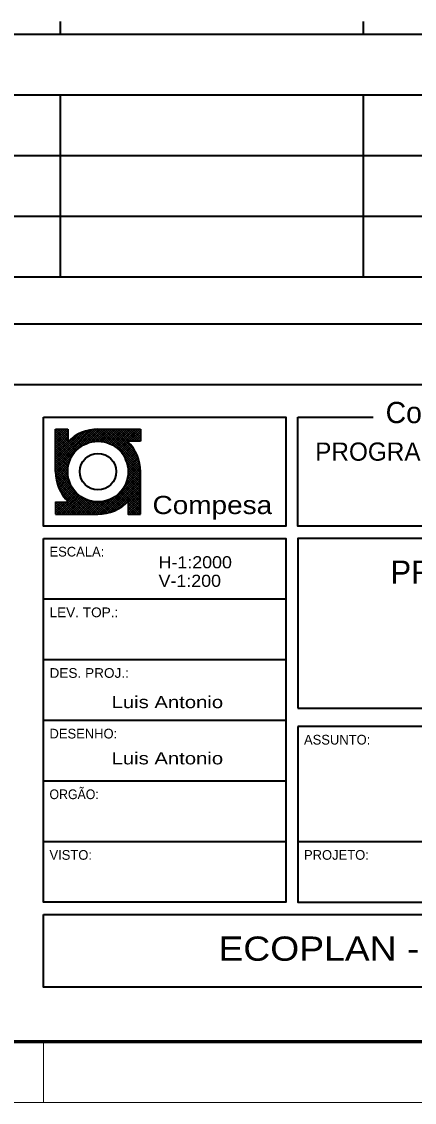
# Model space of a CAD drawing. Extents: x 949 to 2631, y -1701 to -513.
# Drawn here: x 2253.7 to 2383.4, y -1700.7 to -1344.3 of the extents above; entities that cross this region are included whole.
import ezdxf

# ---------------------------------------------------------------- set-up
doc = ezdxf.new("R2010")
doc.units = 0
doc.header["$LTSCALE"] = 1.2
for name, color, linetype, lineweight in [('1', 7, 'Continuous', 13), ('10', 7, 'Continuous', 13), ('11', 7, 'Continuous', 13), ('5', 7, 'Continuous', 13), ('6', 7, 'Continuous', 60), ('7', 7, 'Continuous', 35)]:
    doc.layers.add(name, color=color, linetype=linetype, lineweight=lineweight)

msp = doc.modelspace()

# ---------------------------------------------------------------- linework, layer by layer
at = {"layer": '1'}
for p, q in [((2264.926, -1478.868), (2265.067, -1478.728)), ((2264.926, -1479.575), (2265.774, -1478.728)), ((2264.926, -1480.283), (2266.481, -1478.728)), ((2264.926, -1480.99), (2267.188, -1478.728)), ((2264.926, -1481.697), (2267.895, -1478.728)), ((2264.926, -1482.404), (2268.602, -1478.728)), ((2264.926, -1492.303), (2278.49, -1478.739)), ((2264.926, -1491.596), (2277.739, -1478.783)), ((2264.926, -1490.889), (2276.942, -1478.873)), ((2264.926, -1490.182), (2276.086, -1479.022)), ((2268.926, -1482.694), (2264.959, -1478.728)), ((2268.926, -1481.987), (2265.667, -1478.728)), ((2268.926, -1481.28), (2266.374, -1478.728)), ((2268.926, -1480.573), (2267.081, -1478.728)), ((2268.926, -1479.866), (2267.788, -1478.728)), ((2268.926, -1479.158), (2268.495, -1478.728)), ((2268.926, -1482.93), (2268.926, -1478.728)), ((2273.764, -1484.172), (2279.209, -1478.728)), ((2275.172, -1483.472), (2279.916, -1478.728)), ((2276.243, -1483.108), (2280.623, -1478.728)), ((2280.395, -1482.849), (2276.491, -1478.945)), ((2281.27, -1483.017), (2277.104, -1478.852)), ((2277.162, -1482.896), (2281.33, -1478.728)), ((2282.277, -1483.317), (2277.742, -1478.783)), ((2277.988, -1482.777), (2282.037, -1478.728)), ((2283.535, -1483.868), (2278.408, -1478.741)), ((2278.734, -1482.738), (2282.744, -1478.728)), ((2292.921, -1492.547), (2279.102, -1478.728)), ((2279.425, -1482.754), (2283.451, -1478.728)), ((2292.892, -1491.811), (2279.809, -1478.728)), ((2280.086, -1482.8), (2284.159, -1478.728)), ((2292.819, -1491.03), (2280.516, -1478.728)), ((2280.696, -1482.897), (2284.866, -1478.728)), ((2292.69, -1490.195), (2281.223, -1478.728)), ((2281.281, -1483.02), (2285.573, -1478.728)), ((2281.838, -1483.169), (2286.28, -1478.728)), ((2292.493, -1489.29), (2281.93, -1478.728)), ((2282.364, -1483.351), (2286.987, -1478.728)), ((2292.206, -1488.296), (2282.637, -1478.728)), ((2282.875, -1483.547), (2287.694, -1478.728)), ((2291.759, -1487.142), (2283.344, -1478.728)), ((2283.353, -1483.775), (2288.401, -1478.728)), ((2283.822, -1484.014), (2289.108, -1478.728)), ((2291.041, -1485.717), (2284.051, -1478.728)), ((2284.259, -1484.284), (2289.815, -1478.728)), ((2284.688, -1484.562), (2290.523, -1478.728)), ((2288.758, -1482.728), (2284.758, -1478.728)), ((2285.089, -1484.868), (2291.23, -1478.728)), ((2289.466, -1482.728), (2285.466, -1478.728)), ((2285.48, -1485.185), (2291.937, -1478.728)), ((2285.846, -1485.525), (2292.644, -1478.728)), ((2290.173, -1482.728), (2286.173, -1478.728)), ((2290.88, -1482.728), (2286.88, -1478.728)), ((2291.587, -1482.728), (2287.587, -1478.728)), ((2292.294, -1482.728), (2288.294, -1478.728)), ((2292.926, -1482.652), (2289.001, -1478.728)), ((2292.926, -1481.945), (2289.708, -1478.728)), ((2292.926, -1481.238), (2290.415, -1478.728)), ((2292.926, -1480.531), (2291.122, -1478.728)), ((2292.926, -1479.824), (2291.83, -1478.728)), ((2292.926, -1479.117), (2292.537, -1478.728)), ((2264.926, -1483.111), (2268.926, -1479.111)), ((2264.926, -1489.475), (2275.154, -1479.247)), ((2271.528, -1486.003), (2264.926, -1479.401)), ((2264.926, -1488.768), (2274.105, -1479.589)), ((2264.926, -1483.818), (2268.926, -1479.818)), ((2264.926, -1488.061), (2272.882, -1480.104)), ((2271.208, -1486.39), (2264.926, -1480.108)), ((2264.926, -1484.525), (2268.926, -1480.525)), ((2270.891, -1486.781), (2264.926, -1480.815)), ((2264.926, -1487.354), (2271.269, -1481.01)), ((2264.926, -1485.232), (2268.926, -1481.232)), ((2270.606, -1487.203), (2264.926, -1481.522)), ((2264.926, -1485.939), (2268.926, -1481.939)), ((2270.328, -1487.632), (2264.926, -1482.23)), ((2272.235, -1485.296), (2269.404, -1482.465)), ((2272.626, -1484.979), (2269.78, -1482.134)), ((2273.016, -1484.663), (2270.166, -1481.813)), ((2273.442, -1484.382), (2270.562, -1481.501)), ((2273.871, -1484.103), (2270.976, -1481.209)), ((2274.334, -1483.859), (2271.402, -1480.927)), ((2274.802, -1483.621), (2271.838, -1480.656)), ((2275.308, -1483.419), (2272.292, -1480.403)), ((2275.819, -1483.223), (2272.76, -1480.164)), ((2276.375, -1483.072), (2273.24, -1479.937)), ((2276.941, -1482.931), (2273.737, -1479.727)), ((2277.552, -1482.834), (2274.253, -1479.535)), ((2278.19, -1482.766), (2274.784, -1479.359)), ((2278.862, -1482.731), (2275.331, -1479.2)), ((2279.601, -1482.763), (2275.899, -1479.06)), ((2289.351, -1482.728), (2292.926, -1479.153)), ((2290.058, -1482.728), (2292.926, -1479.86)), ((2290.765, -1482.728), (2292.926, -1480.567)), ((2291.472, -1482.728), (2292.926, -1481.274)), ((2292.179, -1482.728), (2292.926, -1481.981)), ((2264.926, -1486.646), (2268.926, -1482.646)), ((2270.08, -1488.091), (2264.926, -1482.937)), ((2269.842, -1488.56), (2264.926, -1483.644)), ((2269.636, -1489.061), (2264.926, -1484.351)), ((2269.44, -1489.572), (2264.926, -1485.058)), ((2269.285, -1490.124), (2264.926, -1485.765)), ((2271.881, -1485.649), (2269.045, -1482.813)), ((2286.2, -1485.879), (2289.033, -1483.045)), ((2286.533, -1486.253), (2289.372, -1483.414)), ((2286.849, -1486.644), (2289.702, -1483.791)), ((2287.148, -1487.052), (2290.014, -1484.186)), ((2287.426, -1487.481), (2290.314, -1484.593)), ((2287.688, -1487.926), (2290.605, -1485.009)), ((2287.926, -1488.395), (2290.878, -1485.444)), ((2288.147, -1488.882), (2291.137, -1485.891)), ((2292.887, -1482.728), (2292.926, -1482.688)), ((2269.139, -1490.685), (2264.926, -1486.472)), ((2269.042, -1491.295), (2264.926, -1487.179)), ((2268.968, -1491.928), (2264.926, -1487.886)), ((2268.933, -1492.6), (2264.926, -1488.594)), ((2268.957, -1493.332), (2264.926, -1489.301)), ((2264.933, -1493.003), (2270.371, -1487.566)), ((2264.962, -1493.681), (2269.67, -1488.973)), ((2292.926, -1493.259), (2287.785, -1488.118)), ((2292.926, -1493.966), (2288.336, -1489.377)), ((2288.343, -1489.393), (2291.386, -1486.35)), ((2288.514, -1489.928), (2291.618, -1486.825)), ((2288.664, -1490.486), (2291.833, -1487.317)), ((2288.776, -1491.081), (2292.034, -1487.823)), ((2288.872, -1491.692), (2292.221, -1488.343)), ((2288.888, -1493.09), (2292.531, -1489.447)), ((2288.907, -1492.364), (2292.385, -1488.886)), ((2269.035, -1494.117), (2264.926, -1490.008)), ((2269.191, -1494.98), (2264.926, -1490.715)), ((2269.474, -1495.97), (2264.926, -1491.422)), ((2269.997, -1497.2), (2264.926, -1492.129)), ((2271.434, -1499.344), (2264.929, -1492.839)), ((2265.02, -1494.33), (2269.306, -1490.044)), ((2265.104, -1494.953), (2269.095, -1490.963)), ((2265.216, -1495.548), (2268.975, -1491.79)), ((2265.349, -1496.123), (2268.936, -1492.536)), ((2265.5, -1496.679), (2268.952, -1493.227)), ((2287.216, -1498.297), (2292.922, -1492.591)), ((2288.093, -1496.714), (2292.9, -1491.906)), ((2288.493, -1495.606), (2292.847, -1491.252)), ((2292.926, -1494.673), (2288.637, -1490.384)), ((2288.722, -1494.67), (2292.765, -1490.628)), ((2292.926, -1495.38), (2288.804, -1491.259)), ((2288.805, -1493.88), (2292.658, -1490.027)), ((2292.926, -1496.087), (2288.891, -1492.052)), ((2292.926, -1496.795), (2288.919, -1492.788)), ((2278.11, -1506.728), (2264.954, -1493.571)), ((2277.403, -1506.728), (2265.023, -1494.347)), ((2276.696, -1506.728), (2265.146, -1495.178)), ((2275.989, -1506.728), (2265.337, -1496.076)), ((2265.668, -1497.218), (2268.999, -1493.887)), ((2265.856, -1497.737), (2269.096, -1494.498)), ((2266.062, -1498.239), (2269.218, -1495.082)), ((2266.281, -1498.727), (2269.368, -1495.64)), ((2266.513, -1499.202), (2269.549, -1496.166)), ((2266.765, -1499.656), (2269.745, -1496.677)), ((2279.509, -1506.712), (2292.926, -1493.295)), ((2280.268, -1506.66), (2292.926, -1494.002)), ((2281.075, -1506.559), (2292.926, -1494.709)), ((2281.945, -1506.397), (2292.926, -1495.416)), ((2282.903, -1506.146), (2292.926, -1496.123)), ((2283.971, -1505.785), (2292.926, -1496.83)), ((2292.926, -1501.037), (2288.234, -1496.345)), ((2292.926, -1500.33), (2288.43, -1495.834)), ((2292.926, -1499.623), (2288.581, -1495.278)), ((2292.926, -1498.916), (2288.718, -1494.708)), ((2292.926, -1498.209), (2288.785, -1494.068)), ((2292.926, -1497.502), (2288.852, -1493.428)), ((2265.351, -1506.728), (2272.077, -1500.001)), ((2275.282, -1506.728), (2265.616, -1497.061)), ((2274.575, -1506.728), (2266.044, -1498.197)), ((2266.058, -1506.728), (2272.451, -1500.334)), ((2273.868, -1506.728), (2266.727, -1499.587)), ((2267.029, -1500.099), (2269.974, -1497.155)), ((2267.304, -1500.532), (2270.213, -1497.623)), ((2267.597, -1500.946), (2270.482, -1498.061)), ((2267.901, -1501.349), (2270.761, -1498.49)), ((2268.216, -1501.741), (2271.067, -1498.891)), ((2268.547, -1502.117), (2271.383, -1499.281)), ((2268.889, -1502.482), (2271.724, -1499.648)), ((2278.817, -1506.728), (2272.309, -1500.22)), ((2285.249, -1505.214), (2292.926, -1497.537)), ((2288.482, -1502.957), (2285.651, -1500.126)), ((2288.841, -1502.609), (2286.004, -1499.772)), ((2292.926, -1505.987), (2286.358, -1499.419)), ((2292.926, -1505.28), (2286.674, -1499.028)), ((2292.926, -1504.573), (2286.99, -1498.637)), ((2287.04, -1504.13), (2292.926, -1498.244)), ((2292.926, -1503.866), (2287.272, -1498.212)), ((2292.926, -1503.158), (2287.55, -1497.783)), ((2292.926, -1502.451), (2287.794, -1497.32)), ((2292.926, -1501.744), (2288.033, -1496.851)), ((2288.926, -1502.952), (2292.926, -1498.952)), ((2288.926, -1503.659), (2292.926, -1499.659)), ((2288.926, -1504.366), (2292.926, -1500.366)), ((2264.926, -1502.91), (2265.108, -1502.728)), ((2264.926, -1503.617), (2265.815, -1502.728)), ((2264.926, -1504.324), (2266.523, -1502.728)), ((2264.926, -1505.031), (2267.23, -1502.728)), ((2264.926, -1505.738), (2267.937, -1502.728)), ((2264.926, -1506.445), (2268.644, -1502.728)), ((2268.918, -1506.728), (2264.926, -1502.736)), ((2268.211, -1506.728), (2264.926, -1503.443)), ((2269.625, -1506.728), (2265.625, -1502.728)), ((2270.332, -1506.728), (2266.332, -1502.728)), ((2266.765, -1506.728), (2272.842, -1500.651)), ((2271.039, -1506.728), (2267.039, -1502.728)), ((2267.472, -1506.728), (2273.251, -1500.949)), ((2271.746, -1506.728), (2267.746, -1502.728)), ((2268.179, -1506.728), (2273.679, -1501.228)), ((2272.453, -1506.728), (2268.453, -1502.728)), ((2273.16, -1506.728), (2268.52, -1502.088)), ((2268.887, -1506.728), (2274.125, -1501.489)), ((2269.594, -1506.728), (2274.593, -1501.728)), ((2270.301, -1506.728), (2275.08, -1501.948)), ((2271.008, -1506.728), (2275.591, -1502.144)), ((2271.715, -1506.728), (2276.126, -1502.316)), ((2272.422, -1506.728), (2276.684, -1502.465)), ((2273.129, -1506.728), (2277.279, -1502.578)), ((2273.836, -1506.728), (2277.89, -1502.673)), ((2279.509, -1506.712), (2274.454, -1501.657)), ((2274.543, -1506.728), (2278.562, -1502.709)), ((2275.25, -1506.728), (2279.268, -1502.71)), ((2280.172, -1506.668), (2275.684, -1502.18)), ((2275.957, -1506.728), (2280.02, -1502.665)), ((2276.665, -1506.728), (2280.86, -1502.532)), ((2280.807, -1506.596), (2276.674, -1502.463)), ((2277.372, -1506.728), (2281.805, -1502.295)), ((2281.418, -1506.499), (2277.537, -1502.618)), ((2278.079, -1506.728), (2282.912, -1501.894)), ((2282.007, -1506.382), (2278.321, -1502.696)), ((2278.786, -1506.728), (2284.496, -1501.018)), ((2282.575, -1506.242), (2279.053, -1502.721)), ((2283.12, -1506.08), (2279.725, -1502.686)), ((2283.648, -1505.902), (2280.358, -1502.612)), ((2284.162, -1505.708), (2280.969, -1502.515)), ((2284.659, -1505.498), (2281.529, -1502.369)), ((2285.137, -1505.269), (2282.081, -1502.213)), ((2285.603, -1505.028), (2282.592, -1502.017)), ((2286.057, -1504.775), (2283.094, -1501.812)), ((2286.491, -1504.502), (2283.562, -1501.573)), ((2286.915, -1504.219), (2284.022, -1501.326)), ((2287.328, -1503.925), (2284.451, -1501.047)), ((2287.723, -1503.613), (2284.873, -1500.762)), ((2288.108, -1503.29), (2285.263, -1500.446)), ((2288.926, -1505.073), (2292.926, -1501.073)), ((2288.926, -1505.78), (2292.926, -1501.78)), ((2288.926, -1506.487), (2292.926, -1502.487)), ((2292.926, -1506.694), (2288.926, -1502.694)), ((2292.252, -1506.728), (2288.926, -1503.401)), ((2289.393, -1506.728), (2292.926, -1503.194)), ((2290.1, -1506.728), (2292.926, -1503.901)), ((2267.504, -1506.728), (2264.926, -1504.15)), ((2266.797, -1506.728), (2264.926, -1504.857)), ((2266.089, -1506.728), (2264.926, -1505.564)), ((2265.382, -1506.728), (2264.926, -1506.271)), ((2291.545, -1506.728), (2288.926, -1504.108)), ((2290.838, -1506.728), (2288.926, -1504.815)), ((2290.131, -1506.728), (2288.926, -1505.522)), ((2289.424, -1506.728), (2288.926, -1506.23)), ((2290.807, -1506.728), (2292.926, -1504.608)), ((2291.514, -1506.728), (2292.926, -1505.316)), ((2292.221, -1506.728), (2292.926, -1506.023))]:
    msp.add_line(p, q, dxfattribs=at)
for points in [[(2268.926, -1478.728), (2264.926, -1478.728), (2264.926, -1492.728)], [(2288.724, -1482.728), (2292.926, -1482.728), (2292.926, -1478.728), (2278.926, -1478.728)], [(2288.926, -1502.526), (2288.926, -1506.728), (2292.926, -1506.728), (2292.926, -1492.728)], [(2269.128, -1502.728), (2264.926, -1502.728), (2264.926, -1506.728), (2278.926, -1506.728)]]:
    msp.add_lwpolyline(points, dxfattribs=at)
for start, end in [(90, 135.58469), (0, 45.58469), (180, 225.58469), (270, 315.58469)]:
    msp.add_arc((2278.926, -1492.728), 14, start, end, dxfattribs=at)
at = {"layer": '10', "lineweight": 35}
for p, q in [((2264.926, -1492.728), (2264.926, -1478.728)), ((2264.926, -1478.728), (2268.926, -1478.728)), ((2268.926, -1478.728), (2268.926, -1482.93)), ((2278.926, -1478.728), (2292.926, -1478.728)), ((2292.926, -1506.728), (2292.926, -1492.728)), ((2264.926, -1502.728), (2264.926, -1506.728)), ((2264.926, -1506.728), (2278.926, -1506.728)), ((2260.926, -1534.728), (2340.926, -1534.728)), ((2260.926, -1554.728), (2340.926, -1554.728)), ((2260.926, -1574.728), (2340.926, -1574.728)), ((2260.926, -1594.728), (2340.926, -1594.728)), ((2260.926, -1614.728), (2340.926, -1614.728)), ((2344.926, -1614.728), (2592.926, -1614.728))]:
    msp.add_line(p, q, dxfattribs=at)
at = {"layer": '10'}
for p, q in [((2264.926, -1492.728), (2264.926, -1478.728)), ((2264.926, -1478.728), (2268.926, -1478.728)), ((2268.926, -1478.728), (2268.926, -1482.93)), ((2278.926, -1478.728), (2292.926, -1478.728)), ((2270.884, -1486.784), (2272.982, -1484.686)), ((2270.884, -1486.784), (2272.982, -1484.686)), ((2270.969, -1486.671), (2272.869, -1484.771)), ((2270.969, -1486.671), (2272.869, -1484.771)), ((2272.807, -1484.832), (2272.869, -1484.771)), ((2272.956, -1484.712), (2272.982, -1484.686)), ((2270.884, -1486.784), (2270.91, -1486.758)), ((2270.969, -1486.671), (2271.031, -1486.609)), ((2292.926, -1506.728), (2292.926, -1492.728)), ((2284.877, -1500.764), (2286.962, -1498.679)), ((2284.877, -1500.764), (2286.962, -1498.679)), ((2286.934, -1498.707), (2286.962, -1498.679)), ((2269.128, -1502.728), (2264.926, -1502.728)), ((2264.926, -1502.728), (2264.926, -1506.728)), ((2269.128, -1502.728), (2264.926, -1502.728)), ((2268.913, -1502.728), (2269.02, -1502.62)), ((2268.913, -1502.728), (2269.02, -1502.62)), ((2268.913, -1502.728), (2269.02, -1502.62)), ((2268.941, -1502.728), (2269.034, -1502.635)), ((2268.941, -1502.728), (2269.034, -1502.635)), ((2268.941, -1502.728), (2269.034, -1502.635)), ((2284.877, -1500.764), (2284.906, -1500.735)), ((2264.926, -1506.728), (2278.926, -1506.728))]:
    msp.add_line(p, q, dxfattribs=at)
at = {"layer": '10', "lineweight": 35}
msp.add_lwpolyline([(2288.926, -1502.526), (2288.926, -1506.728), (2292.926, -1506.728)], dxfattribs=at)
at = {"layer": '10'}
msp.add_lwpolyline([(2288.926, -1502.526), (2288.926, -1506.728), (2292.926, -1506.728)], dxfattribs=at)
at = {"layer": '10', "lineweight": 35}
for radius in [10, 6]:
    msp.add_circle((2278.926, -1492.728), radius, dxfattribs=at)
for radius, start, end in [(14, 90, 135.58469), (14, 0, 45.58469), (10, 18.00476, 23.99402), (14, 180, 225.58469), (14, 270, 315.58469)]:
    msp.add_arc((2278.926, -1492.728), radius, start, end, dxfattribs=at)
at = {"layer": '10'}
for radius, start, end in [(14, 90, 135.58469), (10, 138.00399, 143.99417), (10, 132.00354, 137.99646), (10, 126.00583, 131.99601), (10, 120.00423, 125.9944), (10, 114.00611, 119.99551), (10, 108.00475, 113.99403), (10, 102.00207, 107.99546), (10, 96.00904, 101.99768), (10, 90.00001, 95.99104), (10, 84.00896, 89.99999), (10, 78.00232, 83.99096), (10, 72.00455, 77.99793), (10, 66.00598, 71.99524), (10, 60.0045, 65.99388), (10, 54.00561, 59.99576), (10, 48.004, 53.99415), (10, 42.00355, 47.99644), (10, 36.00585, 41.99599), (14, 0, 45.58469), (10, 162.00453, 167.99795), (10, 156.00596, 161.99526), (10, 150.00448, 155.9939), (10, 144.00559, 149.99578), (10, 30.00424, 35.99439), (10, 24.00612, 29.9955), (10, 12.00207, 17.99545), (14, 180, 225.58469), (10, 168.0023, 173.99098), (10, 6.00904, 11.99768), (10, 348.00122, 360), (10, 0.00001, 5.99104), (10, 186.00902, 191.9977), (10, 192.00205, 197.99548), (10, 198.00473, 203.99405), (10, 204.00609, 209.99553), (10, 330.00449, 335.99389), (10, 336.00597, 341.99525), (10, 342.00454, 347.99793), (10, 210.00421, 215.99442), (10, 216.00582, 221.99603), (10, 222.00352, 227.99648), (10, 228.00397, 233.99418), (10, 306.00583, 311.99601), (10, 312.00354, 317.99646), (10, 318.00399, 323.99416), (10, 324.0056, 329.99577), (10, 234.00558, 239.99579), (10, 240.00447, 245.99391), (10, 246.00595, 251.99527), (10, 252.00453, 257.99796), (10, 258.00229, 263.99098), (14, 270, 315.58469), (10, 276.00902, 281.9977), (10, 282.00205, 287.99547), (10, 288.00474, 293.99404), (10, 294.0061, 299.99552), (10, 300.00422, 305.99441)]:
    msp.add_arc((2278.926, -1492.728), radius, start, end, dxfattribs=at)
at = {"layer": '11', "lineweight": 35}
for p, q in [((2344.926, -1474.728), (2369.751, -1474.728)), ((2292.926, -1478.728), (2292.926, -1482.728)), ((2292.926, -1482.728), (2288.724, -1482.728))]:
    msp.add_line(p, q, dxfattribs=at)
at = {"layer": '11'}
for p, q in [((2292.926, -1478.728), (2292.926, -1482.728)), ((2292.926, -1482.728), (2288.724, -1482.728)), ((2288.819, -1482.821), (2288.913, -1482.728)), ((2288.819, -1482.821), (2288.913, -1482.728)), ((2288.819, -1482.821), (2288.913, -1482.728)), ((2288.833, -1482.836), (2288.941, -1482.728)), ((2288.833, -1482.836), (2288.941, -1482.728)), ((2288.833, -1482.836), (2288.941, -1482.728))]:
    msp.add_line(p, q, dxfattribs=at)
at = {"layer": '11', "lineweight": 35}
for points in [[(2260.926, -1474.728), (2340.926, -1474.728), (2340.926, -1510.728), (2260.926, -1510.728)], [(2260.926, -1514.728), (2340.926, -1514.728), (2340.926, -1634.728), (2260.926, -1634.728)], [(2344.926, -1570.728), (2592.926, -1570.728), (2592.926, -1514.728), (2344.926, -1514.728)], [(2344.926, -1576.728), (2344.926, -1634.728), (2592.926, -1634.728), (2592.926, -1576.728)], [(2260.926, -1638.728), (2592.926, -1638.728), (2592.926, -1662.728), (2260.926, -1662.728)]]:
    msp.add_lwpolyline(points, close=True, dxfattribs=at)
msp.add_lwpolyline([(2566.158, -1474.728), (2592.926, -1474.728), (2592.926, -1510.728), (2344.926, -1510.728), (2344.926, -1474.728)], dxfattribs=at)
at = {"layer": '5'}
for p, q in [((2260.926, -1700.728), (2260.926, -1680.728)), ((948.926, -1700.728), (2623.017, -1700.728)), ((948.926, -1700.728), (2630.926, -1700.728)), ((948.926, -1700.728), (2630.926, -1700.728))]:
    msp.add_line(p, q, dxfattribs=at)
msp.add_lwpolyline([(948.926, -1700.728), (2630.926, -1700.728), (948.926, -1700.728)], dxfattribs=at)
at = {"layer": '6'}
msp.add_line((2610.926, -1680.728), (998.926, -1680.728), dxfattribs=at)
at = {"layer": '7'}
for p, q in [((2266.405, -1344.336), (2266.405, -1348.501)), ((2366.405, -1344.336), (2366.405, -1348.501)), ((1064.486, -1348.501), (2566.405, -1348.501)), ((1064.486, -1368.501), (2566.405, -1368.501)), ((2066.396, -1368.501), (2566.405, -1368.501)), ((2266.405, -1368.501), (2266.405, -1428.501)), ((2366.405, -1368.501), (2366.405, -1428.501)), ((1064.486, -1388.501), (2566.405, -1388.501)), ((1064.486, -1408.501), (2566.405, -1408.501)), ((1064.486, -1428.501), (2566.405, -1428.501)), ((1064.486, -1443.951), (2566.405, -1443.951)), ((1064.486, -1463.951), (2566.405, -1463.951))]:
    msp.add_line(p, q, dxfattribs=at)

# ---------------------------------------------------------------- texts
at = {"layer": '10'}
for s, height, p in [('Companhia Pernambucana de Saneamento', 7, (2373.865, -1476.728)), ('ESCALA:', 3.2, (2262.926, -1520.728)), ('PROJETO EXECUTIVO DO SISTEMA DE', 7.6, (2375.503, -1529.652)), ('DESENHO:', 3.2, (2262.926, -1580.728)), ('ASSUNTO:', 3.2, (2346.926, -1582.728)), ('VISTO:', 3.2, (2262.926, -1620.728)), ('PROJETO:', 3.2, (2346.926, -1620.728))]:
    msp.add_text(s, height=height, dxfattribs=at).set_placement(p)
for s, height, width, p in [('Compesa', 6, 1.15, (2296.926, -1506.728)), ('H-1:2000', 4, 1.1, (2298.926, -1524.617)), ('V-1:200', 4, 1.1, (2298.926, -1530.728)), ('LEV. TOP.:', 3.2, 1.05, (2262.926, -1540.728)), ('DES. PROJ.:', 3.2, 1.05, (2262.926, -1560.728)), ('Luis Antonio', 4, 1.25, (2283.427, -1570.728)), ('Luis Antonio', 4, 1.25, (2283.427, -1589.269)), ('ORGÃO:', 3.2, 0.95, (2262.926, -1600.728)), ('ECOPLAN - MAIA MELO - ENGECONSULT', 8, 1.15, (2318.686, -1654.025))]:
    msp.add_text(s, height=height, dxfattribs=dict(at, width=width)).set_placement(p)
at = {"layer": '11'}
msp.add_text('PROGRAMA DE AÇÃO SOCIAL EM SANEAMENTO - PASS/BID', height=6, dxfattribs=at).set_placement((2350.619, -1489.13))

doc.saveas('drawing.dxf')
